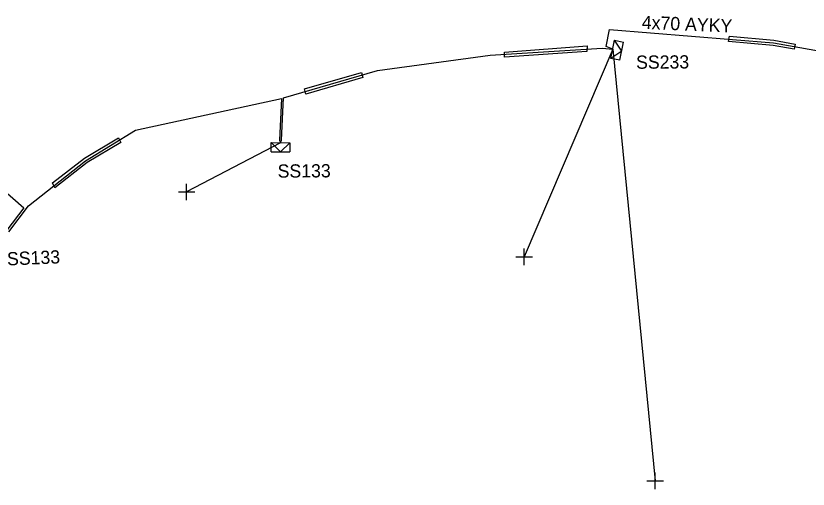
# Model space of a CAD drawing. Extents: x -748492 to -735633, y -1146251 to -1139940.
# Drawn here: x -740052.7 to -739992.7, y -1142071.1 to -1142035.3 of the extents above; entities that cross this region are included whole.
import ezdxf

# ---------------------------------------------------------------- set-up
doc = ezdxf.new("R2010")
doc.units = 0
for name, color, linetype in [('Vrstva 1', 7, 'Continuous'), ('Vrstva 20', 7, 'Continuous'), ('Vrstva 31', 7, 'Continuous'), ('Vrstva 33', 7, 'Continuous'), ('Vrstva 34', 7, 'Continuous'), ('Vrstva 5', 7, 'Continuous'), ('Vrstva 59', 7, 'Continuous'), ('Vrstva 6', 7, 'Continuous'), ('Vrstva 9', 7, 'Continuous')]:
    doc.layers.add(name, color=color, linetype=linetype)

# ---------------------------------------------------------------- blocks, each defined once
blk = doc.blocks.new('NN800')
at = {"layer": 'Vrstva 1'}
for points in [[(-0.442, 0.442), (0.442, -0.442)], [(-0.442, -0.442), (0.442, 0.442)]]:
    blk.add_lwpolyline(points, dxfattribs=at)
blk = doc.blocks.new('NN630')
at = {"layer": 'Vrstva 9'}
for points in [[(-0.003, -0.7), (-0.703, 0)], [(-0.703, -0.7), (-0.703, 0), (0.697, 0), (0.697, -0.7)], [(-0.003, -0.7), (0.697, 0)], [(-0.703, -0.7), (0.697, -0.7)]]:
    blk.add_lwpolyline(points, dxfattribs=at)

msp = doc.modelspace()

# ---------------------------------------------------------------- linework, layer by layer
at = {"layer": 'Vrstva 20'}
for points in [[(-739998.686, -1142036.847), (-739995.35, -1142037.151), (-739993.729, -1142037.438), (-739993.815, -1142037.829), (-739995.382, -1142037.548), (-739998.772, -1142037.237)], [(-740015.723, -1142038.05), (-740009.47, -1142037.578), (-740009.473, -1142037.99), (-740015.704, -1142038.435)], [(-740030.835, -1142040.829), (-740026.518, -1142039.589), (-740026.422, -1142039.978), (-740030.739, -1142041.217)], [(-740044.904, -1142044.533), (-740044.729, -1142044.893), (-740047.276, -1142046.404), (-740049.707, -1142048.306), (-740049.882, -1142047.946), (-740047.477, -1142046.062)]]:
    msp.add_lwpolyline(points, close=True, dxfattribs=at)
at = {"layer": 'Vrstva 5'}
for points in [[(-740053.19, -1142051.654), (-740051.704, -1142049.689), (-740047.39, -1142046.28), (-740043.62, -1142043.95), (-740032.573, -1142041.546), (-740032.721, -1142044.713), (-740032.641, -1142044.9), (-740032.566, -1142044.708), (-740032.418, -1142041.506), (-740025.32, -1142039.44), (-740016.8, -1142038.28), (-740008.316, -1142037.737), (-740007.53, -1142037.83), (-740008.029, -1142037.622), (-740007.76, -1142036.34), (-739995.37, -1142037.34), (-739990.67, -1142038.18), (-739979.485, -1142040.435), (-739979.641, -1142041.124)], [(-740056.04, -1142046.35), (-740052.062, -1142049.82), (-740053.335, -1142051.521)]]:
    msp.add_lwpolyline(points, dxfattribs=at)
at = {"layer": 'Vrstva 59'}
for points in [[(-740007.53, -1142037.829), (-740014.224, -1142053.536)], [(-740007.53, -1142037.829), (-740004.31, -1142070.5)], [(-740032.64, -1142044.9), (-740039.75, -1142048.63)]]:
    msp.add_lwpolyline(points, dxfattribs=at)

# ---------------------------------------------------------------- block references
at = {"layer": 'Vrstva 31'}
for p, rotation in [((-740007.53, -1142037.83), 78.4907722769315), ((-740032.64, -1142044.9), -0.23054723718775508)]:
    msp.add_blockref('NN630', p, dxfattribs=dict(at, rotation=rotation))
at = {"layer": 'Vrstva 34', "rotation": 45}
for p in [(-740039.75, -1142048.63), (-740014.224, -1142053.536), (-740004.31, -1142070.5)]:
    msp.add_blockref('NN800', p, dxfattribs=at)

# ---------------------------------------------------------------- texts
at = {"layer": 'Vrstva 33'}
for s, rotation, p in [('SS233', 0.439, (-740005.757, -1142039.31)), ('SS133', 0.36, (-740032.863, -1142047.548)), ('SS133', 2.357, (-740053.311, -1142054.197))]:
    msp.add_text(s, height=1, rotation=rotation, dxfattribs=at).set_placement(p)
at = {"layer": 'Vrstva 6'}
msp.add_text('4x70 AYKY', height=1, rotation=357.604, dxfattribs=at).set_placement((-740005.342, -1142036.28))

doc.saveas('drawing.dxf')
